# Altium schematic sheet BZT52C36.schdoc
size 127 x 101 mm
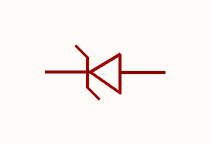
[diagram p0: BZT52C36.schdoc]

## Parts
ZD?  bzt52c36_c21562  [SOD-123_L2.8-W1.8-LS3.7-RD]  (value not drawn)

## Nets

Not connected (* = marked no-connect by the designer): ZD? 1(K) 2(A)

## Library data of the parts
ZD? = bzt52c36_c21562: 二极管配置:1个独立式;稳压值(标称值):36V;稳压值(范围):34V~38V;耗散功率(Pd):500mW;; Manufacturer: CJ(江苏长电/长晶); AddInBom: yes; ModelId: 7884390a25fb4c08947731ebfba7e3f8; ModelTransform: 144.8816,62.992,0,0,0,0,0,0,0; Diode Configuration: 1个独立式; Zener Voltage(Nom): 36V; Reverse Leakage Current (Ir): 100nA; Pd - Power Dissipation: 500mW; Impedance(Zzt): 90Ω; Impedance(Zzk): 350Ω; Operating Junction Temperature Range: -55℃~+150℃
